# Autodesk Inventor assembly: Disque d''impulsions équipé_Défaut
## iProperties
Shininess: 64.0
Length Units: 11269
Angle Units: 11279
Time Units: 11290
Mass Units: 11283
Length Display Precision: 3
Angle Display Precision: 2
Compacted: True
Created: 2006-01
Part Number: Disque d''impulsions équipé_Défaut
Document SubType Name: Assembly
Designer: riri
Density: 0.0
Volumn: 0.0
Area: 0.0
PropertySet Name: Model Information
Control State: 0
Master: False
Checked Out: False
Author: riri
